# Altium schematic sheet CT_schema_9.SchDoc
size 147 x 119 mm
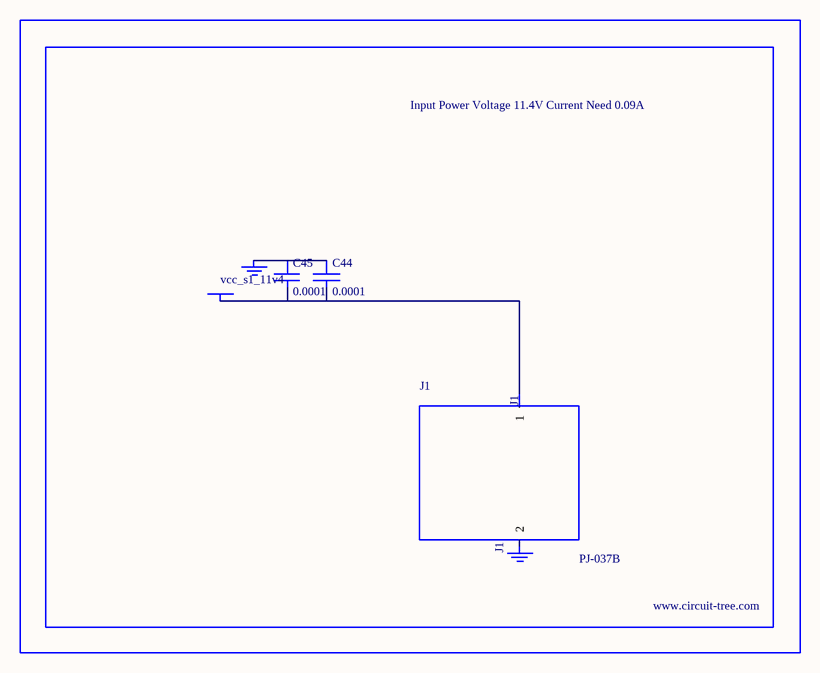
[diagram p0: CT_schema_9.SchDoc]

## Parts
BORDER8  (no value)
C44  0.0001  [EXV-9H]
C45  0.0001  [EXV-9H]
GND_INSTANCE_8_0  (no value)
GND_INSTANCE_8_1  (no value)
J1  PJ-037B  [PJ-037B_PACKAGE]
POWER_INSTANCE_8_0  vcc_s1_11v4

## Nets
NetC44_1: C44.1 C45.1 GND_INSTANCE_8_0.0(GND)
NetC44_2: C44.2 C45.2 J1.1 POWER_INSTANCE_8_0.0(PWR)

Not connected (* = marked no-connect by the designer): GND_INSTANCE_8_1 0(GND); J1 2

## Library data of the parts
BORDER8 = BORDER_PAGE8
C44 C45 = EDK107M035A9HAA
GND_INSTANCE_8_0 GND_INSTANCE_8_1 = GND
POWER_INSTANCE_8_0 = PWR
